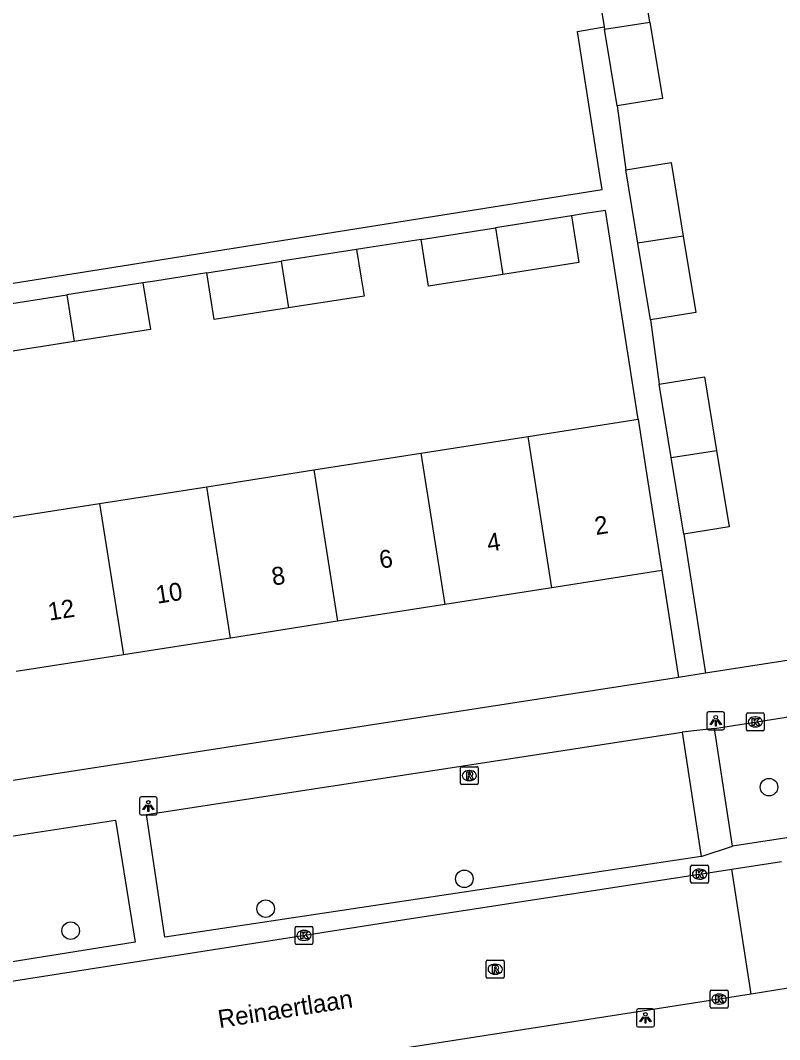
# Model space of a CAD drawing. Extents: x 160077 to 160945, y 386481 to 387498.
# Drawn here: x 160283.4 to 160325.8, y 387353.4 to 387410.3 of the extents above; entities that cross this region are included whole.
import ezdxf

# ---------------------------------------------------------------- set-up
doc = ezdxf.new("R2010")
doc.units = 0
for name, color, linetype in [('IMGEO_Boom', 7, 'Continuous'), ('IMGEO_Kolk', 7, 'Continuous'), ('IMGEO_Lichtpunt', 7, 'Continuous'), ('IMGEO_Openbare_ruimte_label', 7, 'Continuous'), ('IMGEO_Pand', 7, 'Continuous'), ('IMGEO_Pand_nummerreeks', 7, 'Continuous'), ('IMGEO_Rijbaan_lokaal_open', 7, 'Continuous'), ('IMGEO_Rioolput', 7, 'Continuous'), ('IMGEO_Voetpad_open', 7, 'Continuous')]:
    doc.layers.add(name, color=color, linetype=linetype)

msp = doc.modelspace()

# ---------------------------------------------------------------- linework, layer by layer
at = {"layer": 'IMGEO_Boom'}
for centre in [(160325.174, 387367.521), (160308.169, 387362.403), (160297.087, 387360.735), (160286.21, 387359.509)]:
    msp.add_circle(centre, 0.489, dxfattribs=at)
at = {"layer": 'IMGEO_Kolk'}
for p, q in [((160323.907, 387370.733), (160323.907, 387371.585)), ((160323.982, 387371.659), (160324.834, 387371.659)), ((160324.908, 387371.585), (160324.908, 387370.733)), ((160324.395, 387371.439), (160324.42, 387371.439)), ((160324.834, 387370.659), (160323.982, 387370.659)), ((160324.418, 387370.879), (160324.393, 387370.879)), ((160320.796, 387362.237), (160320.796, 387363.089)), ((160320.871, 387363.163), (160321.723, 387363.163)), ((160321.797, 387363.089), (160321.797, 387362.237)), ((160321.284, 387362.943), (160321.309, 387362.943)), ((160321.723, 387362.163), (160320.871, 387362.163)), ((160321.307, 387362.383), (160321.282, 387362.383)), ((160298.724, 387358.819), (160298.724, 387359.671)), ((160298.799, 387359.745), (160299.651, 387359.745)), ((160299.725, 387359.671), (160299.725, 387358.819)), ((160299.212, 387359.525), (160299.237, 387359.525)), ((160299.651, 387358.745), (160298.799, 387358.745)), ((160299.235, 387358.965), (160299.21, 387358.965)), ((160321.961, 387356.191), (160322.813, 387356.191)), ((160321.886, 387355.265), (160321.886, 387356.117)), ((160322.374, 387355.971), (160322.399, 387355.971)), ((160322.887, 387356.117), (160322.887, 387355.265)), ((160322.813, 387355.191), (160321.961, 387355.191)), ((160322.397, 387355.411), (160322.372, 387355.411))]:
    msp.add_line(p, q, dxfattribs=at)
for points in [[(160323.907, 387370.733), (160323.907, 387371.585)], [(160323.982, 387371.659), (160324.834, 387371.659)], [(160324.908, 387371.585), (160324.908, 387370.733)], [(160324.228, 387371.359), (160324.351, 387371.359), (160324.351, 387371.208), (160324.481, 387371.359), (160324.645, 387371.359), (160324.499, 387371.208), (160324.652, 387370.959), (160324.5, 387370.959), (160324.415, 387371.123), (160324.351, 387371.056), (160324.351, 387370.959), (160324.228, 387370.959), (160324.228, 387371.359)], [(160324.834, 387370.659), (160323.982, 387370.659)], [(160320.796, 387362.237), (160320.796, 387363.089)], [(160320.871, 387363.163), (160321.723, 387363.163)], [(160321.797, 387363.089), (160321.797, 387362.237)], [(160321.117, 387362.863), (160321.24, 387362.863), (160321.24, 387362.712), (160321.37, 387362.863), (160321.534, 387362.863), (160321.388, 387362.712), (160321.541, 387362.463), (160321.389, 387362.463), (160321.304, 387362.627), (160321.24, 387362.56), (160321.24, 387362.463), (160321.117, 387362.463), (160321.117, 387362.863)], [(160321.723, 387362.163), (160320.871, 387362.163)], [(160298.724, 387358.819), (160298.724, 387359.671)], [(160298.799, 387359.745), (160299.651, 387359.745)], [(160299.725, 387359.671), (160299.725, 387358.819)], [(160299.045, 387359.445), (160299.168, 387359.445), (160299.168, 387359.294), (160299.298, 387359.445), (160299.462, 387359.445), (160299.316, 387359.294), (160299.469, 387359.045), (160299.317, 387359.045), (160299.232, 387359.209), (160299.168, 387359.142), (160299.168, 387359.045), (160299.045, 387359.045), (160299.045, 387359.445)], [(160299.651, 387358.745), (160298.799, 387358.745)], [(160321.961, 387356.191), (160322.813, 387356.191)], [(160321.886, 387355.265), (160321.886, 387356.117)], [(160322.207, 387355.891), (160322.33, 387355.891), (160322.33, 387355.74), (160322.46, 387355.891), (160322.624, 387355.891), (160322.478, 387355.74), (160322.631, 387355.491), (160322.479, 387355.491), (160322.394, 387355.655), (160322.33, 387355.588), (160322.33, 387355.491), (160322.207, 387355.491), (160322.207, 387355.891)], [(160322.887, 387356.117), (160322.887, 387355.265)], [(160322.813, 387355.191), (160321.961, 387355.191)]]:
    msp.add_lwpolyline(points, dxfattribs=at)
for centre, start, end in [((160323.984, 387371.583), 91.552, 178.448), ((160323.984, 387371.583), 91.552, 178.448), ((160324.832, 387371.583), 1.552, 88.448), ((160324.832, 387371.583), 1.552, 88.448), ((160323.984, 387370.735), 181.552, 268.448), ((160323.984, 387370.735), 181.552, 268.448), ((160324.832, 387370.735), 271.552, 358.448), ((160324.832, 387370.735), 271.552, 358.448), ((160320.873, 387363.087), 91.552, 178.448), ((160320.873, 387363.087), 91.552, 178.448), ((160321.721, 387363.087), 1.552, 88.448), ((160321.721, 387363.087), 1.552, 88.448), ((160320.873, 387362.239), 181.552, 268.448), ((160320.873, 387362.239), 181.552, 268.448), ((160321.721, 387362.239), 271.552, 358.448), ((160321.721, 387362.239), 271.552, 358.448), ((160298.801, 387359.669), 91.552, 178.448), ((160298.801, 387359.669), 91.552, 178.448), ((160299.649, 387359.669), 1.552, 88.448), ((160299.649, 387359.669), 1.552, 88.448), ((160298.801, 387358.821), 181.552, 268.448), ((160298.801, 387358.821), 181.552, 268.448), ((160299.649, 387358.821), 271.552, 358.448), ((160299.649, 387358.821), 271.552, 358.448), ((160321.963, 387356.115), 91.552, 178.448), ((160321.963, 387356.115), 91.552, 178.448), ((160322.811, 387356.115), 1.552, 88.448), ((160322.811, 387356.115), 1.552, 88.448), ((160321.963, 387355.267), 181.552, 268.448), ((160321.963, 387355.267), 181.552, 268.448), ((160322.811, 387355.267), 271.552, 358.448), ((160322.811, 387355.267), 271.552, 358.448)]:
    msp.add_arc(centre, 0.0765, start, end, dxfattribs=at)
for centre, major_axis, ratio, start_param, end_param in [((160324.394, 387371.159), (-0.387, 0.002), 0.722429, 4.712389, 7.853982), ((160324.419, 387371.159), (-0.39, 0.002), 0.717154, 1.570796, 4.712389), ((160321.283, 387362.663), (-0.387, 0.002), 0.722429, 4.712389, 7.853982), ((160321.308, 387362.663), (-0.39, 0.002), 0.717154, 1.570796, 4.712389), ((160299.211, 387359.245), (-0.387, 0.002), 0.722429, 4.712389, 7.853982), ((160299.236, 387359.245), (-0.39, 0.002), 0.717154, 1.570796, 4.712389), ((160322.373, 387355.691), (-0.387, 0.002), 0.722429, 4.712389, 7.853982), ((160322.398, 387355.691), (-0.39, 0.002), 0.717154, 1.570796, 4.712389)]:
    msp.add_ellipse(centre, major_axis=major_axis, ratio=ratio, start_param=start_param, end_param=end_param, dxfattribs=at)
at = {"layer": 'IMGEO_Lichtpunt'}
for p, q in [((160321.7, 387371.624), (160321.7, 387370.817)), ((160321.7, 387371.624), (160321.7, 387370.817)), ((160322.602, 387371.719), (160321.794, 387371.719)), ((160322.602, 387371.719), (160321.794, 387371.719)), ((160322.696, 387370.817), (160322.696, 387371.624)), ((160322.696, 387370.817), (160322.696, 387371.624)), ((160321.794, 387370.723), (160322.602, 387370.723)), ((160321.794, 387370.723), (160322.602, 387370.723)), ((160290.043, 387366.876), (160290.043, 387366.069)), ((160290.043, 387366.876), (160290.043, 387366.069)), ((160290.945, 387366.971), (160290.137, 387366.971)), ((160290.945, 387366.971), (160290.137, 387366.971)), ((160291.039, 387366.069), (160291.039, 387366.876)), ((160291.039, 387366.069), (160291.039, 387366.876)), ((160290.137, 387365.975), (160290.945, 387365.975)), ((160290.137, 387365.975), (160290.945, 387365.975)), ((160318.679, 387355.138), (160317.871, 387355.138)), ((160318.679, 387355.138), (160317.871, 387355.138)), ((160317.777, 387355.043), (160317.777, 387354.236)), ((160317.777, 387355.043), (160317.777, 387354.236)), ((160318.773, 387354.236), (160318.773, 387355.043)), ((160318.773, 387354.236), (160318.773, 387355.043)), ((160317.871, 387354.142), (160318.679, 387354.142)), ((160317.871, 387354.142), (160318.679, 387354.142))]:
    msp.add_line(p, q, dxfattribs=at)
for points in [[(160322.074, 387371.288), (160322.113, 387371.26), (160321.925, 387370.998), (160321.887, 387371.025), (160322.074, 387371.288)], [(160322.176, 387371.24), (160322.223, 387371.24), (160322.223, 387370.918), (160322.176, 387370.918), (160322.176, 387371.24)], [(160322.286, 387371.26), (160322.324, 387371.287), (160322.511, 387371.025), (160322.472, 387370.997), (160322.286, 387371.26)], [(160290.417, 387366.54), (160290.456, 387366.512), (160290.268, 387366.25), (160290.23, 387366.277), (160290.417, 387366.54)], [(160290.519, 387366.492), (160290.566, 387366.492), (160290.566, 387366.17), (160290.519, 387366.17), (160290.519, 387366.492)], [(160290.629, 387366.512), (160290.667, 387366.539), (160290.854, 387366.277), (160290.815, 387366.249), (160290.629, 387366.512)], [(160318.151, 387354.707), (160318.19, 387354.679), (160318.002, 387354.417), (160317.964, 387354.444), (160318.151, 387354.707)], [(160318.253, 387354.659), (160318.3, 387354.659), (160318.3, 387354.337), (160318.253, 387354.337), (160318.253, 387354.659)], [(160318.363, 387354.679), (160318.401, 387354.706), (160318.588, 387354.444), (160318.549, 387354.416), (160318.363, 387354.679)]]:
    msp.add_lwpolyline(points, dxfattribs=at)
for centre in [(160322.199, 387371.422), (160290.542, 387366.674), (160318.276, 387354.841)]:
    msp.add_circle(centre, 0.0994, dxfattribs=at)
for centre, start, end in [((160321.794, 387371.624), 90, 180), ((160321.794, 387371.624), 90, 180), ((160322.602, 387371.624), 0, 90), ((160322.602, 387371.624), 0, 90), ((160321.794, 387370.817), 180, 270), ((160321.794, 387370.817), 180, 270), ((160322.602, 387370.817), 270, 0), ((160322.602, 387370.817), 270, 360), ((160290.137, 387366.876), 90, 180), ((160290.137, 387366.876), 90, 180), ((160290.945, 387366.876), 0, 90), ((160290.945, 387366.876), 0, 90), ((160290.137, 387366.069), 180, 270), ((160290.137, 387366.069), 180, 270), ((160290.945, 387366.069), 270, 0), ((160290.945, 387366.069), 270, 360), ((160317.871, 387355.043), 90, 180), ((160317.871, 387355.043), 90, 180), ((160318.679, 387355.043), 0, 90), ((160318.679, 387355.043), 0, 90), ((160317.871, 387354.236), 180, 270), ((160317.871, 387354.236), 180, 270), ((160318.679, 387354.236), 270, 0), ((160318.679, 387354.236), 270, 360)]:
    msp.add_arc(centre, 0.0946, start, end, dxfattribs=at)
at = {"layer": 'IMGEO_Pand'}
for points in [[(160318.522, 387410.224), (160317.844, 387414.339), (160318.61, 387414.465), (160318.283, 387416.439), (160318.146, 387417.266), (160314.387, 387416.646), (160314.845, 387413.846), (160315.322, 387413.924), (160315.976, 387409.953)], [(160315.976, 387409.953), (160315.996, 387409.831)], [(160315.996, 387409.831), (160318.522, 387410.224)], [(160316.7, 387405.552), (160315.996, 387409.831)], [(160318.522, 387410.224), (160319.223, 387405.967), (160316.7, 387405.552)], [(160317.183, 387401.969), (160319.705, 387402.384), (160320.383, 387398.269)], [(160317.857, 387397.876), (160317.183, 387401.969)], [(160314.152, 387399.412), (160309.904, 387398.744)], [(160314.152, 387399.412), (160314.562, 387396.811), (160310.312, 387396.142)], [(160305.759, 387398.092), (160309.904, 387398.744)], [(160309.904, 387398.744), (160310.312, 387396.142)], [(160310.312, 387396.142), (160306.168, 387395.49), (160305.759, 387398.092)], [(160320.383, 387398.269), (160317.857, 387397.876)], [(160318.561, 387393.597), (160317.857, 387397.876)], [(160320.383, 387398.269), (160321.084, 387394.012), (160318.561, 387393.597)], [(160302.163, 387397.534), (160297.95, 387396.871)], [(160302.163, 387397.534), (160302.398, 387396.042), (160302.573, 387394.932), (160298.358, 387394.269)], [(160293.805, 387396.219), (160297.95, 387396.871)], [(160297.95, 387396.871), (160298.358, 387394.269)], [(160298.358, 387394.269), (160294.214, 387393.617), (160293.805, 387396.219)], [(160290.24, 387395.666), (160285.995, 387394.998)], [(160290.24, 387395.666), (160290.659, 387393.065), (160286.403, 387392.396)], [(160281.851, 387394.346), (160285.995, 387394.998)], [(160285.995, 387394.998), (160286.403, 387392.396)], [(160286.403, 387392.396), (160282.26, 387391.744), (160281.851, 387394.346)], [(160319.043, 387390.013), (160321.565, 387390.428), (160322.244, 387386.305)], [(160319.718, 387385.912), (160319.043, 387390.013)], [(160311.729, 387387.1), (160317.865, 387388.061)], [(160317.865, 387388.061), (160318.414, 387384.555), (160319.188, 387379.615)], [(160305.752, 387386.163), (160311.729, 387387.1)], [(160313.053, 387378.654), (160311.729, 387387.1)], [(160299.775, 387385.227), (160305.752, 387386.163)], [(160305.752, 387386.163), (160307.076, 387377.718)], [(160319.718, 387385.912), (160322.244, 387386.305)], [(160320.421, 387381.641), (160319.718, 387385.912)], [(160322.244, 387386.305), (160322.944, 387382.056), (160320.421, 387381.641)], [(160293.798, 387384.291), (160299.775, 387385.227)], [(160299.775, 387385.227), (160301.099, 387376.781)], [(160287.821, 387383.354), (160293.798, 387384.291)], [(160295.122, 387375.845), (160293.798, 387384.291)], [(160281.843, 387382.418), (160287.821, 387383.354)], [(160287.821, 387383.354), (160289.145, 387374.909)], [(160319.188, 387379.615), (160313.053, 387378.654)], [(160313.053, 387378.654), (160307.076, 387377.718)], [(160307.076, 387377.718), (160301.099, 387376.781)], [(160301.099, 387376.781), (160295.122, 387375.845)], [(160295.122, 387375.845), (160289.145, 387374.909)], [(160289.145, 387374.909), (160283.167, 387373.972)]]:
    msp.add_lwpolyline(points, dxfattribs=at)
at = {"layer": 'IMGEO_Rijbaan_lokaal_open'}
for points in [[(160323.094, 387362.939), (160325.861, 387363.367)], [(160265.535, 387333.801), (160262.397, 387353.48), (160304.367, 387360.049), (160323.094, 387362.939)], [(160324.17, 387355.972), (160323.094, 387362.939)], [(160326.936, 387356.404), (160324.17, 387355.972)], [(160324.17, 387355.972), (160306.164, 387353.162), (160276.556, 387348.583)]]:
    msp.add_lwpolyline(points, dxfattribs=at)
at = {"layer": 'IMGEO_Rioolput'}
for p, q in [((160307.95, 387367.737), (160307.95, 387368.589)), ((160308.025, 387368.663), (160308.877, 387368.663)), ((160308.438, 387368.443), (160308.463, 387368.443)), ((160308.951, 387368.589), (160308.951, 387367.737)), ((160308.877, 387367.663), (160308.025, 387367.663)), ((160308.461, 387367.883), (160308.436, 387367.883)), ((160309.392, 387356.933), (160309.392, 387357.785)), ((160309.467, 387357.859), (160310.319, 387357.859)), ((160309.88, 387357.639), (160309.905, 387357.639)), ((160310.393, 387357.785), (160310.393, 387356.933)), ((160310.319, 387356.859), (160309.467, 387356.859)), ((160309.903, 387357.079), (160309.878, 387357.079))]:
    msp.add_line(p, q, dxfattribs=at)
for points in [[(160307.95, 387367.737), (160307.95, 387368.589)], [(160308.025, 387368.663), (160308.877, 387368.663)], [(160308.539, 387368.361), (160308.287, 387368.363), (160308.287, 387367.963)], [(160308.465, 387368.282), (160308.411, 387368.282), (160308.411, 387368.201)], [(160308.411, 387368.201), (160308.463, 387368.201)], [(160308.951, 387368.589), (160308.951, 387367.737)], [(160308.877, 387367.663), (160308.025, 387367.663)], [(160308.287, 387367.963), (160308.411, 387367.963), (160308.411, 387368.125), (160308.422, 387368.125)], [(160308.469, 387368.096), (160308.54, 387367.963), (160308.68, 387367.963), (160308.615, 387368.089)], [(160309.392, 387356.933), (160309.392, 387357.785)], [(160309.467, 387357.859), (160310.319, 387357.859)], [(160309.981, 387357.557), (160309.729, 387357.559), (160309.729, 387357.159)], [(160309.907, 387357.478), (160309.853, 387357.478), (160309.853, 387357.397)], [(160309.853, 387357.397), (160309.905, 387357.397)], [(160310.393, 387357.785), (160310.393, 387356.933)], [(160310.319, 387356.859), (160309.467, 387356.859)], [(160309.729, 387357.159), (160309.853, 387357.159), (160309.853, 387357.321), (160309.864, 387357.321)], [(160309.911, 387357.292), (160309.982, 387357.159), (160310.122, 387357.159), (160310.057, 387357.285)]]:
    msp.add_lwpolyline(points, dxfattribs=at)
for centre, radius, start, end in [((160308.027, 387368.587), 0.0765, 91.552, 178.448), ((160308.027, 387368.587), 0.0765, 91.552, 178.448), ((160308.447, 387368.39), 0.19, 274.7715, 282.9687), ((160308.471, 387368.186), 0.0964, 77.0061, 93.1865), ((160308.485, 387368.243), 0.0378, 276.6634, 79.6772), ((160308.538, 387368.251), 0.109, 350.3612, 89.416), ((160308.536, 387368.251), 0.112, 277.5842, 350.9817), ((160308.52, 387368.036), 0.108, 29.5134, 73.7905), ((160308.875, 387368.587), 0.0765, 1.552, 88.448), ((160308.875, 387368.587), 0.0765, 1.552, 88.448), ((160308.027, 387367.739), 0.0765, 181.552, 268.448), ((160308.027, 387367.739), 0.0765, 181.552, 268.448), ((160308.421, 387368.072), 0.0533, 26.0293, 88.6989), ((160308.875, 387367.739), 0.0765, 271.552, 358.448), ((160308.875, 387367.739), 0.0765, 271.552, 358.448), ((160309.469, 387357.783), 0.0765, 91.552, 178.448), ((160309.469, 387357.783), 0.0765, 91.552, 178.448), ((160309.889, 387357.586), 0.19, 274.7715, 282.9687), ((160309.913, 387357.382), 0.0964, 77.0061, 93.1865), ((160309.927, 387357.439), 0.0378, 276.6634, 79.6772), ((160309.98, 387357.447), 0.109, 350.3612, 89.416), ((160309.978, 387357.447), 0.112, 277.5842, 350.9817), ((160309.962, 387357.232), 0.108, 29.5134, 73.7905), ((160310.317, 387357.783), 0.0765, 1.552, 88.448), ((160310.317, 387357.783), 0.0765, 1.552, 88.448), ((160309.469, 387356.935), 0.0765, 181.552, 268.448), ((160309.469, 387356.935), 0.0765, 181.552, 268.448), ((160309.863, 387357.268), 0.0533, 26.0293, 88.6989), ((160310.317, 387356.935), 0.0765, 271.552, 358.448), ((160310.317, 387356.935), 0.0765, 271.552, 358.448)]:
    msp.add_arc(centre, radius, start, end, dxfattribs=at)
for centre, major_axis, ratio, start_param, end_param in [((160308.437, 387368.163), (-0.387, 0.002), 0.722429, 4.712389, 7.853982), ((160308.462, 387368.163), (-0.39, 0.002), 0.717154, 1.570796, 4.712389), ((160309.879, 387357.359), (-0.387, 0.002), 0.722429, 4.712389, 7.853982), ((160309.904, 387357.359), (-0.39, 0.002), 0.717154, 1.570796, 4.712389)]:
    msp.add_ellipse(centre, major_axis=major_axis, ratio=ratio, start_param=start_param, end_param=end_param, dxfattribs=at)
at = {"layer": 'IMGEO_Voetpad_open'}
for points in [[(160263.91, 387392.614), (160315.857, 387400.88), (160315.732, 387401.681), (160314.476, 387409.706), (160315.976, 387409.953)], [(160316.7, 387405.552), (160317.183, 387401.969)], [(160317.865, 387388.061), (160316.041, 387399.709), (160314.81, 387399.516), (160314.152, 387399.412)], [(160305.759, 387398.092), (160302.856, 387397.643), (160302.163, 387397.534)], [(160293.805, 387396.219), (160290.902, 387395.77), (160290.24, 387395.666)], [(160318.561, 387393.597), (160319.043, 387390.013)], [(160320.421, 387381.641), (160321.622, 387373.883)], [(160319.188, 387379.615), (160320.112, 387373.649)], [(160344.769, 387377.466), (160321.622, 387373.883)], [(160321.622, 387373.883), (160320.112, 387373.649)], [(160320.112, 387373.649), (160260.008, 387364.344)], [(160322.124, 387370.799), (160332.373, 387372.412), (160332.601, 387370.967)], [(160321.38, 387363.654), (160291.454, 387359.142), (160290.437, 387365.998), (160320.333, 387370.594)], [(160322.124, 387370.799), (160320.333, 387370.594)], [(160320.333, 387370.594), (160321.38, 387363.654)], [(160323.128, 387364.228), (160322.124, 387370.799)], [(160343.545, 387367.349), (160323.128, 387364.228)], [(160263.782, 387361.836), (160288.707, 387365.672), (160289.797, 387358.867), (160265.038, 387354.902)], [(160321.38, 387363.654), (160323.128, 387364.228)]]:
    msp.add_lwpolyline(points, dxfattribs=at)

# ---------------------------------------------------------------- texts
at = {"layer": 'IMGEO_Openbare_ruimte_label'}
msp.add_text('Reinaertlaan', height=1, rotation=8.8594, dxfattribs=at).set_placement((160294.507, 387354.069))
at = {"layer": 'IMGEO_Pand_nummerreeks'}
for s, p in [('2', (160315.519, 387381.59)), ('4', (160309.512, 387380.65)), ('6', (160303.503, 387379.709)), ('8', (160297.499, 387378.768)), ('10', (160291.035, 387377.755)), ('12', (160285.02, 387376.813))]:
    msp.add_text(s, height=1, rotation=8.9034, dxfattribs=at).set_placement(p)

doc.saveas('drawing.dxf')
